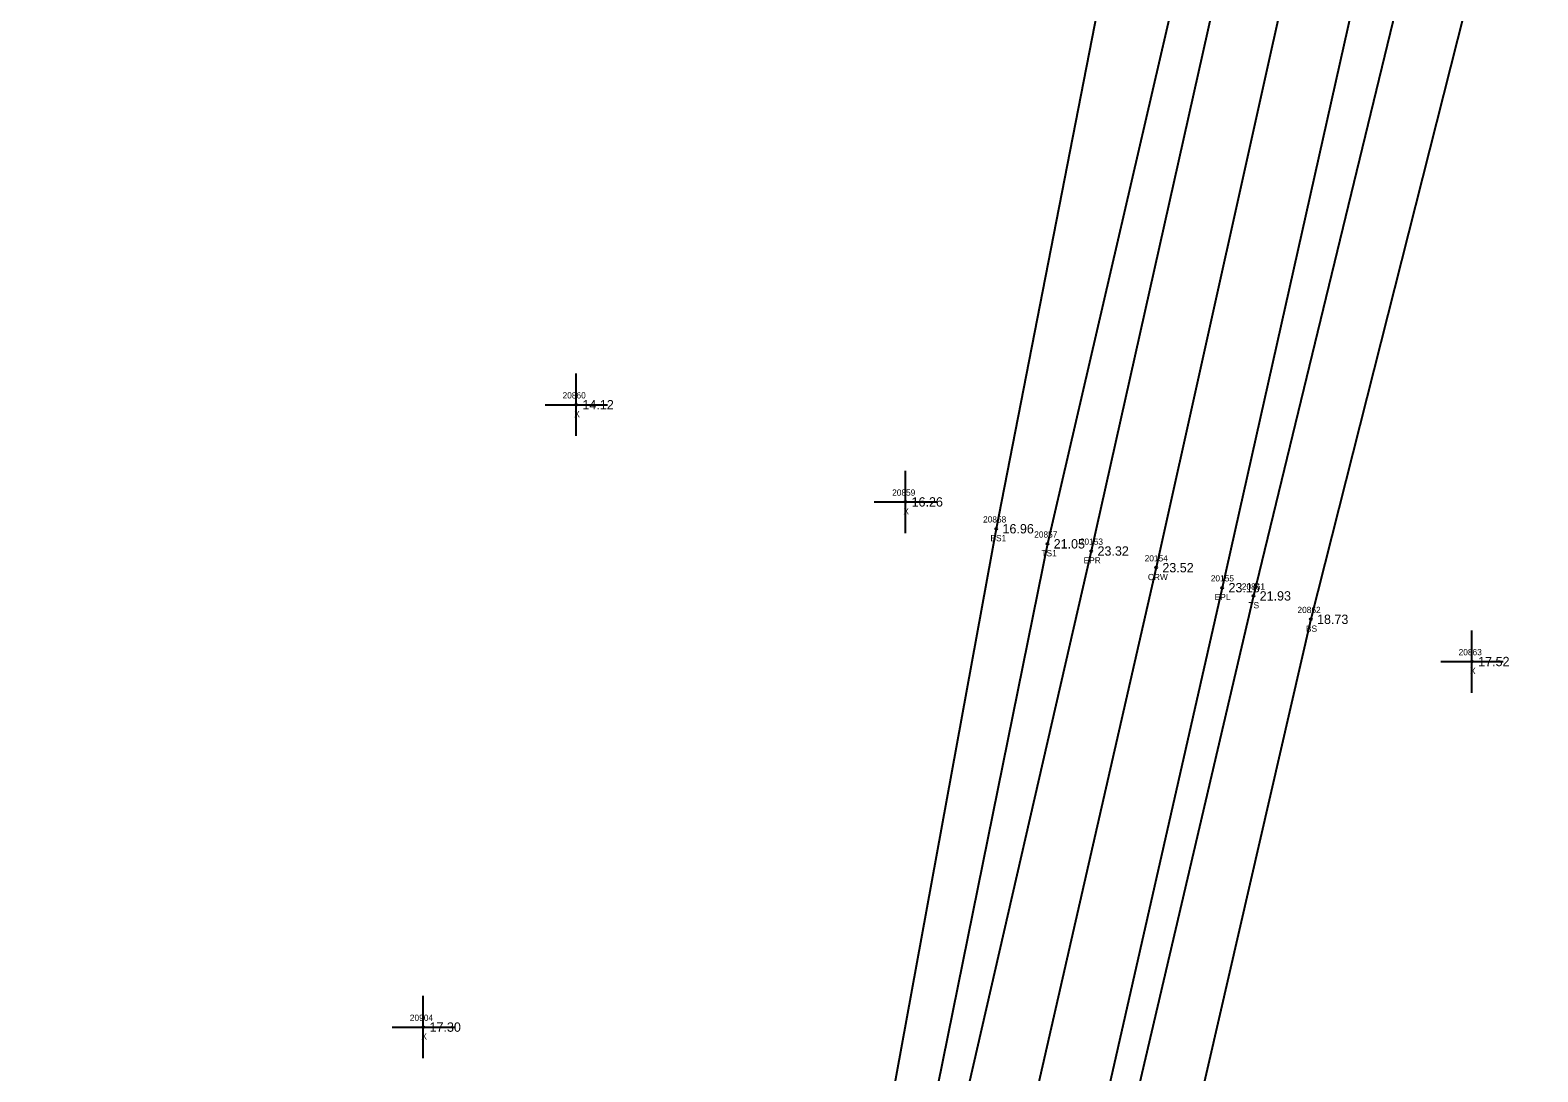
# Model space of a CAD drawing. Extents: x 2655177 to 2656219, y 761780 to 764748.
# Drawn here: x 2655478.9 to 2655720.6, y 762917.5 to 763084.6 of the extents above; entities that cross this region are included whole.
import ezdxf

# ---------------------------------------------------------------- set-up
doc = ezdxf.new("R2010")
doc.units = 0
for name, color, linetype in [('RD_DTM_BkLn1', 7, 'Continuous'), ('RD_DTM_BkLn2', 7, 'Continuous'), ('RD_DTM_BkLn_txCode', 7, 'Continuous'), ('RD_EX_Misc', 7, 'Continuous'), ('RD_EX_Misc_txCode', 7, 'Continuous'), ('RD_EX_Road', 7, 'Continuous'), ('RD_EX_Road_txCode', 7, 'Continuous'), ('RD_EX_TX_Misc_ELEV', 7, 'Continuous'), ('RD_EX_TX_Road_ELEV', 7, 'Continuous'), ('RD_HC_Survey_ELEV', 7, 'Continuous'), ('RD_HC_Survey_txCode', 7, 'Continuous'), ('RD_SMD_Locator', 7, 'Continuous')]:
    doc.layers.add(name, color=color, linetype=linetype)

msp = doc.modelspace()

# ---------------------------------------------------------------- linework, layer by layer
at = {"layer": 'RD_DTM_BkLn1'}
msp.add_lwpolyline([(2655711.06, 763230.3), (2655703.38, 763195.9), (2655681.97, 763099.65), (2655659.44, 762998.39), (2655637.72, 762903.26), (2655615.94, 762806.28), (2655593.94, 762710.45), (2655572.67, 762616.37), (2655551.12, 762519.58), (2655528.83, 762422.13), (2655507.58, 762326.81), (2655486.01, 762234.2), (2655464.77, 762141.12), (2655442.2, 762047.28), (2655420.99, 761952.95), (2655398.79, 761855.74), (2655384.11, 761791.21)], dxfattribs=at)
at = {"layer": 'RD_DTM_BkLn2'}
for points in [[(2655696.84, 763233.58), (2655686.81, 763240.78), (2655674.65, 763210.56), (2655653.92, 763107.89), (2655633.81, 763004.63), (2655616.28, 762908.76), (2655599.96, 762833.02), (2655596.17, 762819.9)], [(2655696.84, 763233.58), (2655686.68, 763198.57), (2655665.58, 763104.06), (2655642.01, 763002.21), (2655622.83, 762907.53), (2655603.3, 762831.47), (2655596.17, 762819.9)], [(2655744.66, 763205.12), (2655733.04, 763202.26), (2655726.56, 763191.09), (2655699.62, 763095.24), (2655675.04, 762993.86), (2655652.95, 762899.23), (2655637.71, 762835.65)], [(2655744.66, 763205.12), (2655742.37, 763185.6), (2655710.01, 763092), (2655684.24, 762990.11), (2655662.96, 762897.71), (2655647.29, 762849.4)]]:
    msp.add_lwpolyline(points, dxfattribs=at)
at = {"layer": 'RD_EX_Misc'}
for p, q in [((2655566.46, 763019.52), (2655566.46, 763029.52)), ((2655561.46, 763024.52), (2655571.46, 763024.52)), ((2655619.23, 763003.93), (2655619.23, 763013.93)), ((2655614.23, 763008.93), (2655624.23, 763008.93)), ((2655710.08, 762978.34), (2655710.08, 762988.34)), ((2655705.08, 762983.34), (2655715.08, 762983.34)), ((2655541.94, 762919.72), (2655541.94, 762929.72)), ((2655536.94, 762924.72), (2655546.94, 762924.72))]:
    msp.add_line(p, q, dxfattribs=at)
at = {"layer": 'RD_EX_Road'}
for points in [[(2655700.99, 763232.28), (2655693.55, 763198.57), (2655671.65, 763102.04), (2655649.04, 763001.06), (2655627.27, 762906.23), (2655605, 762809.37), (2655598.99, 762783.09), (2655583.65, 762714.14), (2655561.97, 762618.32), (2655556.36, 762593.84), (2655548.11, 762557.14), (2655540.1, 762522.48), (2655518.03, 762425.04), (2655496.48, 762329.56), (2655475.55, 762236.62), (2655473.2, 762226.14), (2655466.57, 762197.5), (2655460.06, 762168.16), (2655454.26, 762143.78), (2655432.5, 762049.88), (2655410.7, 761955.51), (2655388.17, 761858.43), (2655373.5, 761793.95)], [(2655722.66, 763227.87), (2655714.47, 763193.23), (2655692.89, 763097.26), (2655670.04, 762995.18), (2655648.57, 762900.67), (2655631.27, 762824.03), (2655626.67, 762802.87), (2655621.78, 762781.91), (2655611.71, 762738.43), (2655604.93, 762708.62), (2655582.64, 762610.54), (2655576.46, 762583.32), (2655561.41, 762517.24)]]:
    msp.add_lwpolyline(points, dxfattribs=at)
at = {"layer": 'RD_SMD_Locator'}
for centre in [(2655566.46, 763024.52), (2655619.23, 763008.93), (2655633.81, 763004.63), (2655642.01, 763002.21), (2655649.04, 763001.06), (2655659.44, 762998.39), (2655670.04, 762995.18), (2655675.04, 762993.86), (2655684.24, 762990.11), (2655710.08, 762983.34), (2655541.94, 762924.72)]:
    msp.add_circle(centre, 0.15, dxfattribs=at)

# ---------------------------------------------------------------- texts
at = {"layer": 'RD_DTM_BkLn_txCode'}
for s, p in [('20858', (2655631.69, 763005.63)), ('BS1', (2655632.87, 763002.63)), ('20857', (2655639.89, 763003.21)), ('TS1', (2655641.05, 763000.21)), ('20861', (2655673.18, 762994.86)), ('TS', (2655674.24, 762991.86)), ('20862', (2655682.1, 762991.11)), ('BS', (2655683.46, 762988.11))]:
    msp.add_text(s, height=1, dxfattribs=at).set_placement(p)
at = {"layer": 'RD_EX_Misc_txCode'}
for s, p in [('20860', (2655564.27, 763025.52)), ('X', (2655566.14, 763022.52)), ('20859', (2655617.11, 763009.93)), ('X', (2655618.92, 763006.93)), ('20863', (2655707.94, 762984.34)), ('X', (2655709.77, 762981.34)), ('20904', (2655539.78, 762925.72)), ('X', (2655541.63, 762922.72))]:
    msp.add_text(s, height=1, dxfattribs=at).set_placement(p)
at = {"layer": 'RD_EX_Road_txCode'}
for s, p in [('20153', (2655647.2, 763002.06)), ('EPR', (2655647.81, 762999.06)), ('20155', (2655668.2, 762996.18)), ('EPL', (2655668.83, 762993.18))]:
    msp.add_text(s, height=1, dxfattribs=at).set_placement(p)
at = {"layer": 'RD_EX_TX_Misc_ELEV'}
for s, p in [('14.12', (2655567.46, 763023.77)), ('16.26', (2655620.23, 763008.18)), ('16.96', (2655634.81, 763003.88)), ('21.05', (2655643.01, 763001.46)), ('21.93', (2655676.04, 762993.11)), ('18.73', (2655685.24, 762989.36)), ('17.52', (2655711.08, 762982.59)), ('17.30', (2655542.94, 762923.97))]:
    msp.add_text(s, height=1.5, dxfattribs=at).set_placement(p)
at = {"layer": 'RD_EX_TX_Road_ELEV'}
for s, p in [('23.32', (2655650.04, 763000.31)), ('23.16', (2655671.04, 762994.43))]:
    msp.add_text(s, height=1.5, dxfattribs=at).set_placement(p)
at = {"layer": 'RD_HC_Survey_ELEV'}
msp.add_text('23.52', height=1.5, dxfattribs=at).set_placement((2655660.44, 762997.64))
at = {"layer": 'RD_HC_Survey_txCode'}
for s, p in [('20154', (2655657.6, 762999.39)), ('CRW', (2655658.12, 762996.39))]:
    msp.add_text(s, height=1, dxfattribs=at).set_placement(p)

doc.saveas('drawing.dxf')
